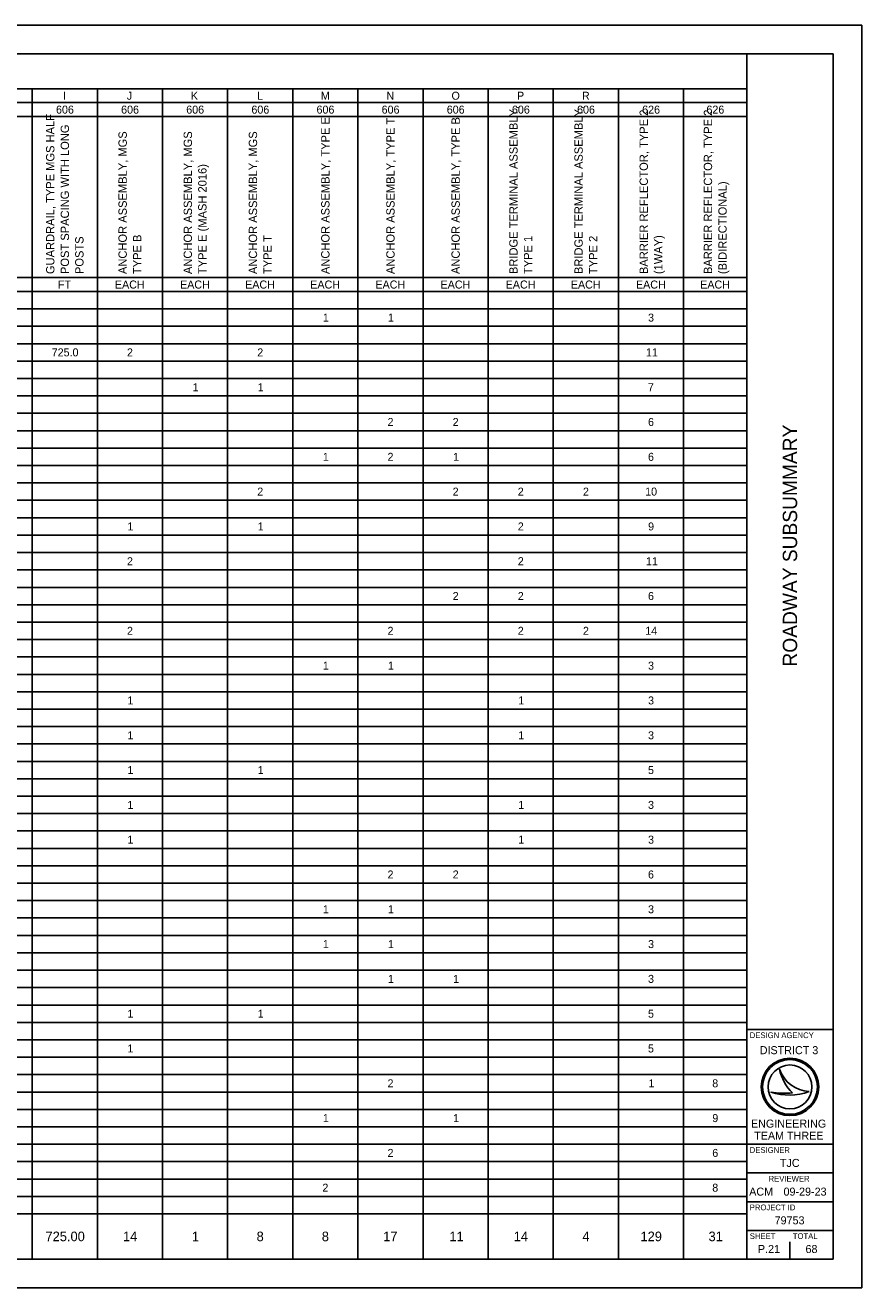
# Model space of a CAD drawing. Extents: x 0 to 34, y 0 to 22.
# Drawn here: x 19.43 to 34, y 0 to 22 of the extents above; entities that cross this region are included whole.
import ezdxf

# ---------------------------------------------------------------- set-up
doc = ezdxf.new("R2010")
doc.units = 0
for name, color, linetype in [('SH_Border', 7, 'Continuous'), ('SH_Cut_Line', 7, 'Continuous'), ('SH_Data', 7, 'Continuous'), ('SH_Text', 7, 'Continuous')]:
    doc.layers.add(name, color=color, linetype=linetype)

msp = doc.modelspace()

# ---------------------------------------------------------------- linework, layer by layer
at = {"layer": 'SH_Border'}
for p, q in [((32, 0.5), (32, 21.5)), ((32, 4.5), (33.5, 4.5)), ((32, 2.5), (33.5, 2.5)), ((32, 2), (33.5, 2)), ((32, 1.5), (33.5, 1.5)), ((32, 1), (33.5, 1))]:
    msp.add_line(p, q, dxfattribs=at)
msp.add_lwpolyline([(1.5, 21.5), (33.5, 21.5), (33.5, 0.5), (1.5, 0.5)], close=True, dxfattribs=at)
at = {"layer": 'SH_Cut_Line'}
msp.add_lwpolyline([(0, 0), (34, 0), (34, 22), (0, 22)], close=True, dxfattribs=at)
at = {"layer": 'SH_Data'}
for p, q in [((32.567, 3.81), (32.567, 3.81)), ((32.417, 3.41), (32.417, 3.41)), ((32.75, 3.5), (32.75, 3.5)), ((33.087, 3.419), (33.087, 3.419)), ((32.375, 0.675), (32.375, 0.675)), ((32.75, 0.5), (32.75, 0.8))]:
    msp.add_line(p, q, dxfattribs=at)
for radius in [0.5, 0.477, 0.477, 0.382]:
    msp.add_circle((32.75, 3.5), radius, dxfattribs=at)
for centre, radius, start, end in [((33.116, 3.998), 0.58, 198.9257, 198.9319), ((33.347, 3.97), 0.796, 191.6379, 191.6421), ((33.116, 3.998), 0.58, 198.9319, 267.1657), ((33.347, 3.97), 0.796, 191.6421, 226.0947), ((32.739, 4.37), 1.013, 251.4576, 290.0832), ((32.648, 4.654), 1.266, 259.4964, 259.4995), ((32.739, 4.37), 1.013, 251.4527, 251.4576), ((32.648, 4.654), 1.266, 259.4995, 276.6672)]:
    msp.add_arc(centre, radius, start, end, dxfattribs=at)
at = {"layer": 'SH_Text'}
for p, q in [((1.5, 21.5), (32, 21.5)), ((32, 21.5), (32, 0.5)), ((1.5, 20.894), (32, 20.894)), ((19.554, 20.894), (19.554, 1.288)), ((20.689, 20.894), (20.689, 1.288)), ((21.823, 20.894), (21.823, 1.288)), ((22.957, 20.894), (22.957, 1.288)), ((24.091, 20.894), (24.091, 1.288)), ((25.226, 20.894), (25.226, 1.288)), ((26.36, 20.894), (26.36, 1.288)), ((27.494, 20.894), (27.494, 1.288)), ((28.629, 20.894), (28.629, 1.288)), ((29.763, 20.894), (29.763, 1.288)), ((30.897, 20.894), (30.897, 1.288)), ((7.77, 20.651), (32, 20.651)), ((7.77, 20.408), (32, 20.408)), ((7.77, 17.603), (32, 17.603)), ((1.5, 17.361), (32, 17.361)), ((1.5, 17.057), (32, 17.057)), ((1.5, 16.754), (32, 16.754)), ((1.5, 16.451), (32, 16.451)), ((1.5, 16.148), (32, 16.148)), ((1.5, 15.844), (32, 15.844)), ((1.5, 15.541), (32, 15.541)), ((1.5, 15.238), (32, 15.238)), ((1.5, 14.935), (32, 14.935)), ((1.5, 14.631), (32, 14.631)), ((1.5, 14.328), (32, 14.328)), ((1.5, 14.025), (32, 14.025)), ((1.5, 13.722), (32, 13.722)), ((1.5, 13.418), (32, 13.418)), ((1.5, 13.115), (32, 13.115)), ((1.5, 12.812), (32, 12.812)), ((1.5, 12.509), (32, 12.509)), ((1.5, 12.205), (32, 12.205)), ((1.5, 11.902), (32, 11.902)), ((1.5, 11.599), (32, 11.599)), ((1.5, 11.296), (32, 11.296)), ((1.5, 10.992), (32, 10.992)), ((1.5, 10.689), (32, 10.689)), ((1.5, 10.386), (32, 10.386)), ((1.5, 10.083), (32, 10.083)), ((1.5, 9.779), (32, 9.779)), ((1.5, 9.476), (32, 9.476)), ((1.5, 9.173), (32, 9.173)), ((1.5, 8.87), (32, 8.87)), ((1.5, 8.566), (32, 8.566)), ((1.5, 8.263), (32, 8.263)), ((1.5, 7.96), (32, 7.96)), ((1.5, 7.657), (32, 7.657)), ((1.5, 7.353), (32, 7.353)), ((1.5, 7.05), (32, 7.05)), ((1.5, 6.747), (32, 6.747)), ((1.5, 6.444), (32, 6.444)), ((1.5, 6.14), (32, 6.14)), ((1.5, 5.837), (32, 5.837)), ((1.5, 5.534), (32, 5.534)), ((1.5, 5.231), (32, 5.231)), ((1.5, 4.927), (32, 4.927)), ((1.5, 4.624), (32, 4.624)), ((1.5, 4.321), (32, 4.321)), ((1.5, 4.018), (32, 4.018)), ((1.5, 3.714), (32, 3.714)), ((1.5, 3.411), (32, 3.411)), ((1.5, 3.108), (32, 3.108)), ((1.5, 2.805), (32, 2.805)), ((1.5, 2.501), (32, 2.501)), ((1.5, 2.198), (32, 2.198)), ((1.5, 1.895), (32, 1.895)), ((1.5, 1.592), (32, 1.592)), ((1.5, 1.288), (32, 1.288)), ((19.554, 1.288), (19.554, 0.5)), ((20.689, 1.288), (20.689, 0.5)), ((21.823, 1.288), (21.823, 0.5)), ((22.957, 1.288), (22.957, 0.5)), ((24.091, 1.288), (24.091, 0.5)), ((25.226, 1.288), (25.226, 0.5)), ((26.36, 1.288), (26.36, 0.5)), ((27.494, 1.288), (27.494, 0.5)), ((28.629, 1.288), (28.629, 0.5)), ((29.763, 1.288), (29.763, 0.5)), ((30.897, 1.288), (30.897, 0.5)), ((1.5, 0.5), (32, 0.5))]:
    msp.add_line(p, q, dxfattribs=at)

# ---------------------------------------------------------------- texts
at = {"layer": 'SH_Data'}
msp.add_text('ROADWAY SUBSUMMARY', height=0.25, rotation=90, dxfattribs=at).set_placement((32.875, 10.824))
for s, height, p in [('DESIGN AGENCY', 0.1, (32.05, 4.35)), ('DISTRICT 3', 0.14, (32.224, 4.07)), ('ENGINEERING', 0.14, (32.071, 2.79)), ('TEAM THREE', 0.14, (32.127, 2.58)), ('DESIGNER', 0.1, (32.05, 2.35)), ('TJC', 0.14, (32.575, 2.105)), ('REVIEWER', 0.1, (32.378, 1.85)), ('ACM', 0.14, (32.04, 1.605)), ('09-29-23', 0.14, (32.638, 1.605)), ('PROJECT ID', 0.1, (32.05, 1.35)), ('79753', 0.14, (32.483, 1.105)), ('SHEET', 0.1, (32.05, 0.85)), ('TOTAL', 0.1, (32.8, 0.85)), ('P.21', 0.14, (32.192, 0.605)), ('68', 0.14, (33.021, 0.605))]:
    msp.add_text(s, height=height, dxfattribs=at).set_placement(p)
at = {"layer": 'SH_Text'}
for s, height, p in [('I', 0.139, (20.091, 20.702)), ('J', 0.139, (21.201, 20.702)), ('K', 0.139, (22.317, 20.702)), ('L', 0.139, (23.471, 20.702)), ('M', 0.139, (24.58, 20.702)), ('N', 0.139, (25.723, 20.702)), ('O', 0.139, (26.856, 20.702)), ('P', 0.139, (27.997, 20.702)), ('R', 0.139, (29.128, 20.702)), ('606', 0.1395, (19.968, 20.46)), ('606', 0.1395, (21.102, 20.46)), ('606', 0.1395, (22.236, 20.46)), ('606', 0.1395, (23.371, 20.46)), ('606', 0.1395, (24.505, 20.46)), ('606', 0.1395, (25.639, 20.46)), ('606', 0.1395, (26.773, 20.46)), ('606', 0.1395, (27.908, 20.46)), ('606', 0.1395, (29.042, 20.46)), ('626', 0.1395, (30.176, 20.46)), ('626', 0.1395, (31.295, 20.46)), ('FT', 0.1395, (20.001, 17.412)), ('EACH', 0.1395, (20.994, 17.412)), ('EACH', 0.1395, (22.128, 17.412)), ('EACH', 0.1395, (23.262, 17.412)), ('EACH', 0.1395, (24.396, 17.412)), ('EACH', 0.1395, (25.531, 17.412)), ('EACH', 0.1395, (26.665, 17.412)), ('EACH', 0.1395, (27.799, 17.412)), ('EACH', 0.1395, (28.934, 17.412)), ('EACH', 0.1395, (30.068, 17.412)), ('EACH', 0.1395, (31.187, 17.412)), ('1', 0.139, (24.615, 16.836)), ('1', 0.139, (25.749, 16.836)), ('3', 0.139, (30.279, 16.836)), ('725.0', 0.1395, (19.893, 16.23)), ('2', 0.139, (21.204, 16.23)), ('2', 0.139, (23.473, 16.23)), ('11', 0.1395, (30.243, 16.23)), ('1', 0.139, (22.346, 15.623)), ('1', 0.139, (23.481, 15.623)), ('7', 0.139, (30.276, 15.623)), ('2', 0.139, (25.742, 15.017)), ('2', 0.139, (26.876, 15.017)), ('6', 0.139, (30.278, 15.017)), ('1', 0.139, (24.615, 14.41)), ('2', 0.139, (25.742, 14.41)), ('1', 0.139, (26.884, 14.41)), ('6', 0.139, (30.278, 14.41)), ('2', 0.139, (23.473, 13.804)), ('2', 0.139, (26.876, 13.804)), ('2', 0.139, (28.01, 13.804)), ('2', 0.139, (29.145, 13.804)), ('10', 0.1395, (30.228, 13.804)), ('1', 0.139, (21.212, 13.197)), ('1', 0.139, (23.481, 13.197)), ('2', 0.139, (28.01, 13.197)), ('9', 0.139, (30.28, 13.197)), ('2', 0.139, (21.204, 12.591)), ('2', 0.139, (28.01, 12.591)), ('11', 0.1395, (30.243, 12.591)), ('2', 0.139, (26.876, 11.984)), ('2', 0.139, (28.01, 11.984)), ('6', 0.139, (30.278, 11.984)), ('2', 0.139, (21.204, 11.378)), ('2', 0.139, (25.742, 11.378)), ('2', 0.139, (28.01, 11.378)), ('2', 0.139, (29.145, 11.378)), ('14', 0.1395, (30.23, 11.378)), ('1', 0.139, (24.615, 10.771)), ('1', 0.139, (25.749, 10.771)), ('3', 0.139, (30.279, 10.771)), ('1', 0.139, (21.212, 10.165)), ('1', 0.139, (28.018, 10.165)), ('3', 0.139, (30.279, 10.165)), ('1', 0.139, (21.212, 9.558)), ('1', 0.139, (28.018, 9.558)), ('3', 0.139, (30.279, 9.558)), ('1', 0.139, (21.212, 8.952)), ('1', 0.139, (23.481, 8.952)), ('5', 0.139, (30.278, 8.952)), ('1', 0.139, (21.212, 8.345)), ('1', 0.139, (28.018, 8.345)), ('3', 0.139, (30.279, 8.345)), ('1', 0.139, (21.212, 7.739)), ('1', 0.139, (28.018, 7.739)), ('3', 0.139, (30.279, 7.739)), ('2', 0.139, (25.742, 7.132)), ('2', 0.139, (26.876, 7.132)), ('6', 0.139, (30.278, 7.132)), ('1', 0.139, (24.615, 6.526)), ('1', 0.139, (25.749, 6.526)), ('3', 0.139, (30.279, 6.526)), ('1', 0.139, (24.615, 5.919)), ('1', 0.139, (25.749, 5.919)), ('3', 0.139, (30.279, 5.919)), ('1', 0.139, (25.749, 5.313)), ('1', 0.139, (26.884, 5.313)), ('3', 0.139, (30.279, 5.313)), ('1', 0.139, (21.212, 4.706)), ('1', 0.139, (23.481, 4.706)), ('5', 0.139, (30.278, 4.706)), ('1', 0.139, (21.212, 4.1)), ('5', 0.139, (30.278, 4.1)), ('2', 0.139, (25.742, 3.493)), ('1', 0.139, (30.286, 3.493)), ('8', 0.139, (31.397, 3.493)), ('1', 0.139, (24.615, 2.887)), ('1', 0.139, (26.884, 2.887)), ('9', 0.139, (31.398, 2.887)), ('2', 0.139, (25.742, 2.28)), ('6', 0.139, (31.397, 2.28)), ('2', 0.139, (24.607, 1.674)), ('8', 0.139, (31.397, 1.674)), ('725.00', 0.1674, (19.785, 0.811)), ('14', 0.1674, (21.134, 0.811)), ('1', 0.167, (22.334, 0.811)), ('8', 0.167, (23.462, 0.811)), ('8', 0.167, (24.597, 0.811)), ('17', 0.1674, (25.666, 0.811)), ('11', 0.1674, (26.819, 0.811)), ('14', 0.1674, (27.939, 0.811)), ('4', 0.167, (29.135, 0.811)), ('129', 0.1674, (30.147, 0.811)), ('31', 0.1674, (31.332, 0.811))]:
    msp.add_text(s, height=height, dxfattribs=at).set_placement(p)
for s, height, p in [('BRIDGE TERMINAL ASSEMBLY, ', 0.14494, (28.007, 17.664)), ('BRIDGE TERMINAL ASSEMBLY, ', 0.14494, (29.141, 17.664)), ('BARRIER REFLECTOR, TYPE 2 ', 0.14494, (30.276, 17.664)), ('BARRIER REFLECTOR, TYPE 2 ', 0.14494, (31.394, 17.664)), ('GUARDRAIL, TYPE MGS HALF ', 0.14494, (19.94, 17.664)), ('POST SPACING WITH LONG ', 0.14494, (20.194, 17.664)), ('ANCHOR ASSEMBLY, TYPE E', 0.14494, (24.731, 17.664)), ('ANCHOR ASSEMBLY, TYPE T', 0.14494, (25.865, 17.664)), ('ANCHOR ASSEMBLY, TYPE B', 0.14494, (27, 17.664)), ('ANCHOR ASSEMBLY, MGS ', 0.14494, (21.201, 17.664)), ('ANCHOR ASSEMBLY, MGS ', 0.14494, (22.336, 17.664)), ('ANCHOR ASSEMBLY, MGS ', 0.14494, (23.47, 17.664)), ('TYPE E (MASH 2016)', 0.14494, (22.589, 17.664)), ('(BIDIRECTIONAL)', 0.14494, (31.648, 17.664)), ('POSTS', 0.1449, (20.447, 17.664)), ('TYPE B', 0.1449, (21.455, 17.664)), ('TYPE T', 0.1449, (23.724, 17.664)), ('TYPE 1', 0.1449, (28.261, 17.664)), ('TYPE 2', 0.1449, (29.395, 17.664)), ('(1WAY)', 0.1449, (30.529, 17.664))]:
    msp.add_text(s, height=height, rotation=90, dxfattribs=at).set_placement(p)

doc.saveas('drawing.dxf')
